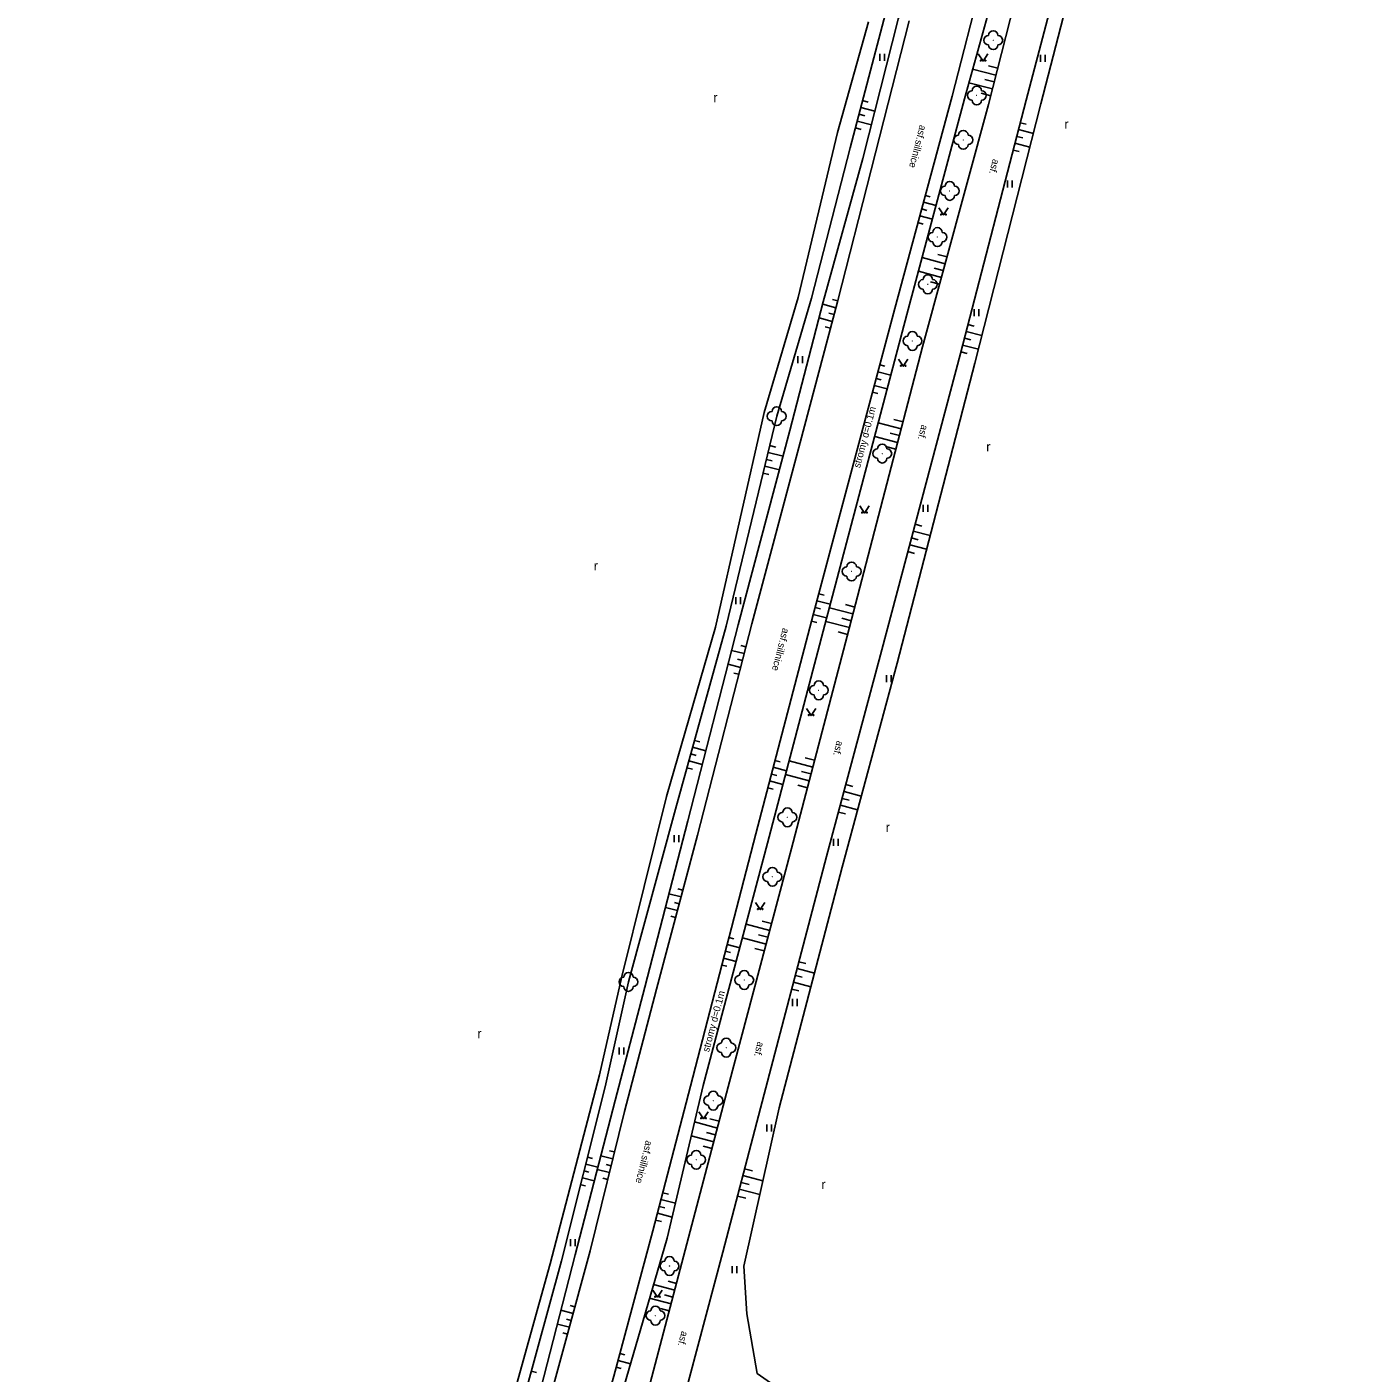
# Model space of a CAD drawing. Extents: x -544674 to -541478, y -1199076 to -1195527.
# Drawn here: x -543780.2 to -543639.1, y -1196517.3 to -1196374.7 of the extents above; entities that cross this region are included whole.
import ezdxf

# ---------------------------------------------------------------- set-up
doc = ezdxf.new("R2010")
doc.units = 0
for name, color, linetype in [('POMOC_POPIS', 7, 'Continuous'), ('ROZHRANÍ_PLOCH', 7, 'Continuous'), ('VÝŠKOPIS', 7, 'Continuous'), ('ZELEŇ', 7, 'Continuous'), ('ZN_KULTUR', 7, 'Continuous')]:
    doc.layers.add(name, color=color, linetype=linetype)

msp = doc.modelspace()

# ---------------------------------------------------------------- linework, layer by layer
at = {"layer": 'ROZHRANÍ_PLOCH'}
for points in [[(-543713.94, -1196502.29), (-543709.96, -1196486.96), (-543703.04, -1196460.2), (-543696.91, -1196436.86), (-543688.3, -1196404.54), (-543682.23, -1196382.06), (-543675.78, -1196357.01), (-543668.72, -1196330.57), (-543660.24, -1196299.58), (-543653.67, -1196274.57), (-543648.76, -1196256.23)], [(-543710.32, -1196503.65), (-543705.94, -1196487.01), (-543699.25, -1196461.77), (-543693.35, -1196439.26), (-543685.35, -1196408.6), (-543678.38, -1196382.95), (-543671.9, -1196357.54), (-543664.83, -1196330.47), (-543656.54, -1196299.56), (-543650.01, -1196274.95), (-543645.18, -1196256.3)], [(-543706.53, -1196504.53), (-543702.52, -1196489.26), (-543695.52, -1196462.6), (-543689.68, -1196440.73), (-543681.35, -1196409.31), (-543674.39, -1196382.48), (-543667.96, -1196358.03), (-543660.58, -1196330.51), (-543652.53, -1196299.96), (-543646.07, -1196275.64), (-543641, -1196257.05)], [(-543686.78, -1196374.08), (-543690.8, -1196389.86), (-543694.38, -1196403.86), (-543698.34, -1196418.74), (-543703.44, -1196437.95), (-543709.2, -1196460.36), (-543713.55, -1196476.67), (-543716.95, -1196489.63), (-543720.59, -1196504.4), (-543725.61, -1196522.92), (-543729.11, -1196534.77), (-543733.49, -1196548.27), (-543738.89, -1196562.11), (-543744.58, -1196575.93), (-543749.39, -1196586.97), (-543754.95, -1196599.21), (-543755.34, -1196599.22), (-543756.54, -1196598.46), (-543756.94, -1196599.56), (-543760.03, -1196600.31), (-543763.62, -1196598.81)], [(-543729.73, -1196565.54), (-543730.89, -1196565.83), (-543732.83, -1196565.23), (-543733.3, -1196563.99), (-543732.97, -1196562.92), (-543728.03, -1196551.04), (-543722.51, -1196533.16), (-543718.06, -1196517.68), (-543713.94, -1196502.29)], [(-543729.73, -1196565.54), (-543725.15, -1196555.44), (-543719.77, -1196539.74), (-543714.56, -1196519.74), (-543710.32, -1196503.65)], [(-543710.94, -1196521.13), (-543706.53, -1196504.53)]]:
    msp.add_lwpolyline(points, dxfattribs=at)
at = {"layer": 'VÝŠKOPIS'}
for points in [[(-543656.57, -1196252.62), (-543662.82, -1196274.48), (-543668.53, -1196296.88), (-543674.74, -1196318.16), (-543679.23, -1196336.73), (-543684.9, -1196357.49), (-543689.3, -1196373.31), (-543693.03, -1196387.54), (-543697.13, -1196403.44), (-543700.81, -1196415.96), (-543706.15, -1196438.21), (-543711.55, -1196457.59), (-543716.52, -1196475.9), (-543718.99, -1196487.01), (-543723.6, -1196505.47), (-543727.55, -1196519.79), (-543731.43, -1196534.94), (-543734.91, -1196546.82), (-543740.91, -1196561.15), (-543746.57, -1196574.16), (-543754.01, -1196590.99), (-543756.54, -1196598.46)], [(-543655.56, -1196252.24), (-543661.88, -1196275.79), (-543667.34, -1196296.39), (-543673.37, -1196318.85), (-543677.88, -1196336.4), (-543683.81, -1196358.79), (-543687.96, -1196373.9), (-543691.68, -1196388.67), (-543695.88, -1196403.86), (-543699.42, -1196417.47), (-543704.89, -1196438.05), (-543710.23, -1196458.84), (-543714.8, -1196476.45), (-543717.94, -1196488.46), (-543722.17, -1196504.83), (-543726.47, -1196521.6), (-543730.21, -1196534.99), (-543734.23, -1196547.47), (-543745.4, -1196574.89), (-543750.67, -1196586.8), (-543755.95, -1196598.6)], [(-543712.43, -1196503.05), (-543708.6, -1196486.87), (-543701.78, -1196461.21), (-543695.71, -1196438.06), (-543687.01, -1196405.18), (-543680.92, -1196382.32), (-543674.04, -1196357.52), (-543666.62, -1196330.61), (-543658.6, -1196299.62), (-543651.87, -1196274.66), (-543647, -1196256.04)], [(-543677.4, -1196379.1), (-543678.38, -1196378.85)], [(-543677.58, -1196379.83), (-543680.05, -1196379.2)], [(-543677.77, -1196380.55), (-543678.76, -1196380.3)], [(-543677.95, -1196381.28), (-543680.45, -1196380.64)], [(-543678.14, -1196382.01), (-543679.15, -1196381.75)], [(-543691.9, -1196383.24), (-543690.41, -1196383.63)], [(-543691.71, -1196382.52), (-543691.12, -1196382.67)], [(-543692.28, -1196384.69), (-543690.78, -1196385.09)], [(-543692.09, -1196383.97), (-543691.49, -1196384.12)], [(-543692.47, -1196385.42), (-543691.87, -1196385.58)], [(-543675.19, -1196385.58), (-543673.62, -1196385.99)], [(-543675.01, -1196384.86), (-543674.38, -1196385.02)], [(-543675.57, -1196387.03), (-543673.99, -1196387.45)], [(-543675.38, -1196386.31), (-543674.75, -1196386.47)], [(-543675.76, -1196387.76), (-543675.13, -1196387.93)], [(-543685.06, -1196392.56), (-543684.54, -1196392.7)], [(-543685.45, -1196394), (-543684.92, -1196394.15)], [(-543685.26, -1196393.28), (-543683.93, -1196393.64)], [(-543685.85, -1196395.45), (-543685.31, -1196395.6)], [(-543685.65, -1196394.73), (-543684.32, -1196395.09)], [(-543682.76, -1196399.08), (-543683.74, -1196398.82)], [(-543682.96, -1196399.81), (-543685.4, -1196399.14)], [(-543683.16, -1196400.53), (-543684.13, -1196400.26)], [(-543683.35, -1196401.25), (-543685.79, -1196400.59)], [(-543683.55, -1196401.98), (-543684.52, -1196401.71)], [(-543694.54, -1196404.47), (-543695.94, -1196404.1)], [(-543694.35, -1196403.74), (-543694.91, -1196403.6)], [(-543694.93, -1196405.92), (-543696.32, -1196405.55)], [(-543694.73, -1196405.19), (-543695.29, -1196405.04)], [(-543695.12, -1196406.64), (-543695.68, -1196406.49)], [(-543680.74, -1196406.97), (-543679.07, -1196407.4)], [(-543680.55, -1196406.24), (-543679.89, -1196406.42)], [(-543681.12, -1196408.42), (-543679.44, -1196408.86)], [(-543680.93, -1196407.7), (-543680.26, -1196407.87)], [(-543681.31, -1196409.15), (-543680.64, -1196409.32)], [(-543690.09, -1196411.25), (-543688.71, -1196411.61)], [(-543689.89, -1196410.52), (-543689.34, -1196410.67)], [(-543690.47, -1196412.69), (-543689.1, -1196413.06)], [(-543690.28, -1196411.97), (-543689.73, -1196412.12)], [(-543690.67, -1196413.42), (-543690.11, -1196413.57)], [(-543687.62, -1196417.29), (-543690.05, -1196416.65)], [(-543687.43, -1196416.56), (-543688.4, -1196416.31)], [(-543688, -1196418.74), (-543690.43, -1196418.1)], [(-543687.81, -1196418.01), (-543688.78, -1196417.76)], [(-543701.73, -1196419.81), (-543700.14, -1196420.19)], [(-543701.56, -1196419.08), (-543700.92, -1196419.24)], [(-543688.18, -1196419.46), (-543689.16, -1196419.21)], [(-543702.08, -1196421.27), (-543700.53, -1196421.64)], [(-543701.91, -1196420.54), (-543701.28, -1196420.69)], [(-543702.26, -1196422), (-543701.64, -1196422.15)], [(-543686.15, -1196427.41), (-543685.44, -1196427.6)], [(-543686.53, -1196428.86), (-543685.82, -1196429.05)], [(-543686.34, -1196428.13), (-543684.56, -1196428.6)], [(-543686.92, -1196430.31), (-543686.2, -1196430.5)], [(-543686.72, -1196429.58), (-543684.93, -1196430.06)], [(-543696.55, -1196435.51), (-543695.13, -1196435.88)], [(-543696.36, -1196434.78), (-543695.79, -1196434.93)], [(-543692.55, -1196436.18), (-543693.54, -1196435.92)], [(-543696.94, -1196436.96), (-543695.52, -1196437.33)], [(-543696.74, -1196436.23), (-543696.18, -1196436.38)], [(-543692.74, -1196436.9), (-543695.23, -1196436.25)], [(-543692.92, -1196437.63), (-543693.92, -1196437.37)], [(-543697.13, -1196437.68), (-543696.56, -1196437.83)], [(-543693.11, -1196438.36), (-543695.62, -1196437.7)], [(-543693.3, -1196439.08), (-543694.3, -1196438.82)], [(-543704.07, -1196440.4), (-543704.6, -1196440.26)], [(-543704.26, -1196441.12), (-543705.59, -1196440.78)], [(-543704.44, -1196441.85), (-543704.98, -1196441.71)], [(-543704.63, -1196442.58), (-543705.96, -1196442.23)], [(-543704.82, -1196443.3), (-543705.35, -1196443.17)], [(-543709.52, -1196450.31), (-543708.97, -1196450.46)], [(-543709.92, -1196451.75), (-543709.36, -1196451.91)], [(-543709.72, -1196451.03), (-543708.32, -1196451.42)], [(-543710.12, -1196452.48), (-543708.7, -1196452.87)], [(-543701.19, -1196453.16), (-543699.77, -1196453.54)], [(-543701, -1196452.44), (-543700.43, -1196452.59)], [(-543696.99, -1196453.14), (-543699.49, -1196452.49)], [(-543696.8, -1196452.42), (-543697.8, -1196452.16)], [(-543710.33, -1196453.2), (-543709.75, -1196453.36)], [(-543701.38, -1196453.89), (-543700.81, -1196454.04)], [(-543697.37, -1196454.59), (-543699.87, -1196453.94)], [(-543697.18, -1196453.87), (-543698.18, -1196453.61)], [(-543701.76, -1196455.34), (-543701.19, -1196455.49)], [(-543701.57, -1196454.61), (-543700.15, -1196454.99)], [(-543697.56, -1196455.32), (-543698.56, -1196455.06)], [(-543693.68, -1196455.72), (-543691.85, -1196456.22)], [(-543693.49, -1196455), (-543692.75, -1196455.2)], [(-543694.07, -1196457.17), (-543692.24, -1196457.66)], [(-543693.88, -1196456.45), (-543693.14, -1196456.65)], [(-543694.26, -1196457.9), (-543693.53, -1196458.09)], [(-543710.94, -1196466.89), (-543712.23, -1196466.55)], [(-543710.75, -1196466.17), (-543711.27, -1196466.03)], [(-543711.33, -1196468.34), (-543712.61, -1196468)], [(-543711.14, -1196467.62), (-543711.65, -1196467.48)], [(-543711.52, -1196469.07), (-543712.03, -1196468.93)], [(-543701.55, -1196470.45), (-543704.06, -1196469.78)], [(-543701.36, -1196469.72), (-543702.36, -1196469.46)], [(-543705.88, -1196471.2), (-543705.34, -1196471.34)], [(-543701.93, -1196471.9), (-543704.44, -1196471.23)], [(-543701.74, -1196471.17), (-543702.75, -1196470.91)], [(-543706.26, -1196472.65), (-543705.72, -1196472.79)], [(-543706.07, -1196471.93), (-543704.72, -1196472.28)], [(-543702.13, -1196472.62), (-543703.13, -1196472.36)], [(-543706.64, -1196474.11), (-543706.1, -1196474.24)], [(-543706.45, -1196473.38), (-543705.11, -1196473.73)], [(-543698.64, -1196474.49), (-543696.81, -1196474.97)], [(-543698.45, -1196473.76), (-543697.72, -1196473.95)], [(-543699.02, -1196475.94), (-543697.19, -1196476.42)], [(-543698.83, -1196475.21), (-543698.1, -1196475.4)], [(-543699.21, -1196476.66), (-543698.48, -1196476.86)], [(-543707.09, -1196491.38), (-543709.52, -1196490.74)], [(-543706.9, -1196490.66), (-543707.88, -1196490.4)], [(-543707.47, -1196492.83), (-543709.86, -1196492.2)], [(-543707.28, -1196492.11), (-543708.24, -1196491.85)], [(-543720.85, -1196494.48), (-543720.34, -1196494.6)], [(-543718.19, -1196494.64), (-543719.46, -1196494.33)], [(-543718.01, -1196493.91), (-543718.51, -1196493.79)], [(-543707.66, -1196493.56), (-543708.61, -1196493.31)], [(-543721.22, -1196495.93), (-543720.71, -1196496.06)], [(-543721.04, -1196495.2), (-543719.76, -1196495.52)], [(-543718.54, -1196496.1), (-543719.83, -1196495.78)], [(-543718.36, -1196495.37), (-543718.88, -1196495.24)], [(-543704.21, -1196495.69), (-543703.37, -1196495.91)], [(-543721.58, -1196497.39), (-543721.08, -1196497.51)], [(-543721.4, -1196496.66), (-543720.14, -1196496.97)], [(-543718.72, -1196496.83), (-543719.24, -1196496.7)], [(-543704.59, -1196497.14), (-543703.73, -1196497.36)], [(-543704.4, -1196496.41), (-543702.28, -1196496.97)], [(-543712.89, -1196498.23), (-543712.28, -1196498.39)], [(-543704.97, -1196498.59), (-543704.09, -1196498.82)], [(-543704.78, -1196497.86), (-543702.61, -1196498.43)], [(-543713.26, -1196499.68), (-543712.65, -1196499.84)], [(-543713.08, -1196498.96), (-543711.55, -1196499.35)], [(-543713.64, -1196501.14), (-543713.01, -1196501.3)], [(-543713.45, -1196500.41), (-543711.9, -1196500.81)], [(-543731.34, -1196564.06), (-543726.83, -1196552.9), (-543721.06, -1196533.73), (-543717.02, -1196518.81), (-543712.43, -1196503.05)], [(-543711.62, -1196508.57), (-543713.86, -1196507.97)], [(-543711.42, -1196507.84), (-543712.32, -1196507.61)], [(-543722.19, -1196510.32), (-543722.71, -1196510.18)], [(-543712, -1196510.02), (-543714.28, -1196509.42)], [(-543711.81, -1196509.29), (-543712.71, -1196509.05)], [(-543722.39, -1196511.04), (-543723.67, -1196510.69)], [(-543722.59, -1196511.77), (-543723.1, -1196511.63)], [(-543712.19, -1196510.74), (-543713.11, -1196510.5)], [(-543722.78, -1196512.49), (-543724.05, -1196512.15)], [(-543722.98, -1196513.21), (-543723.48, -1196513.08)], [(-543717.42, -1196515.28), (-543716.89, -1196515.42)], [(-543726.82, -1196517.14), (-543726.26, -1196517.29)], [(-543717.81, -1196516.73), (-543717.29, -1196516.87)], [(-543717.61, -1196516.01), (-543716.31, -1196516.36)]]:
    msp.add_lwpolyline(points, dxfattribs=at)
at = {"layer": 'ZELEŇ'}
for points in [[(-543688.28, -1196527.59), (-543702.87, -1196517.4), (-543703.99, -1196511.08), (-543704.31, -1196506.02), (-543700.55, -1196489.23), (-543693.87, -1196463.75), (-543688.06, -1196442.12), (-543679.82, -1196410.33), (-543672.82, -1196382.86), (-543666.5, -1196358.38), (-543659.09, -1196330.75), (-543650.58, -1196299.71), (-543644.42, -1196276.01), (-543639.11, -1196257.26)], [(-543691.1, -1196374.18), (-543694.38, -1196385.9), (-543698.54, -1196403.39), (-543702.15, -1196415.58), (-543707.3, -1196438.33), (-543712.47, -1196456.25), (-543717.21, -1196475.32), (-543719.59, -1196485.76), (-543724.81, -1196505.77), (-543728.19, -1196517.96), (-543732.69, -1196534.82), (-543736.53, -1196544.77), (-543742.92, -1196560.89), (-543747.83, -1196573.44), (-543753.43, -1196587.09), (-543757.29, -1196589.64), (-543761.72, -1196591.39), (-543770.74, -1196589.32), (-543780.25, -1196585.27)]]:
    msp.add_lwpolyline(points, dxfattribs=at)
for centre in [(-543677.87, -1196376.12), (-543679.61, -1196381.98), (-543681.04, -1196386.68), (-543682.47, -1196392.09), (-543683.78, -1196396.98), (-543684.8, -1196401.99), (-543686.43, -1196407.99), (-543700.81, -1196415.96), (-543689.63, -1196419.92), (-543692.87, -1196432.41), (-543696.35, -1196445), (-543699.68, -1196458.46), (-543701.27, -1196464.76), (-543716.52, -1196475.9), (-543704.25, -1196475.7), (-543706.15, -1196482.87), (-543707.53, -1196488.48), (-543709.34, -1196494.75), (-543712.17, -1196506), (-543713.66, -1196511.26)]:
    msp.add_circle(centre, 0.0005, dxfattribs=at)
for centre, start, end in [((-543678.37, -1196376.12), 89.99999, 269.99999), ((-543677.87, -1196375.62), 0, 179.99999), ((-543677.37, -1196376.12), 270, 89.99999), ((-543677.87, -1196376.62), 179.99999, 359.99999), ((-543680.11, -1196381.98), 89.99999, 269.99999), ((-543679.61, -1196381.48), 0, 179.99999), ((-543679.11, -1196381.98), 270, 89.99999), ((-543679.61, -1196382.48), 179.99999, 359.99999), ((-543681.04, -1196386.18), 0, 179.99999), ((-543681.54, -1196386.68), 89.99999, 269.99999), ((-543681.04, -1196387.18), 179.99999, 359.99999), ((-543680.54, -1196386.68), 270, 89.99999), ((-543682.97, -1196392.09), 89.99999, 269.99999), ((-543682.47, -1196391.59), 0, 179.99999), ((-543681.97, -1196392.09), 270, 89.99999), ((-543682.47, -1196392.59), 179.99999, 359.99999), ((-543683.78, -1196396.48), 0, 179.99999), ((-543684.28, -1196396.98), 89.99999, 269.99999), ((-543683.78, -1196397.48), 179.99999, 359.99999), ((-543683.28, -1196396.98), 270, 89.99999), ((-543685.3, -1196401.99), 89.99999, 269.99999), ((-543684.8, -1196401.49), 0, 179.99999), ((-543684.3, -1196401.99), 270, 89.99999), ((-543684.8, -1196402.49), 179.99999, 359.99999), ((-543686.93, -1196407.99), 89.99999, 269.99999), ((-543686.43, -1196407.49), 0, 179.99999), ((-543685.93, -1196407.99), 270, 89.99999), ((-543686.43, -1196408.49), 179.99999, 359.99999), ((-543701.31, -1196415.96), 89.99999, 269.99999), ((-543700.81, -1196415.46), 0, 179.99999), ((-543700.31, -1196415.96), 270, 89.99999), ((-543700.81, -1196416.46), 179.99999, 359.99999), ((-543689.63, -1196419.42), 0, 179.99999), ((-543690.13, -1196419.92), 89.99999, 269.99999), ((-543689.13, -1196419.92), 270, 89.99999), ((-543689.63, -1196420.42), 179.99999, 359.99999), ((-543692.87, -1196431.91), 0, 179.99999), ((-543693.37, -1196432.41), 89.99999, 269.99999), ((-543692.87, -1196432.91), 179.99999, 359.99999), ((-543692.37, -1196432.41), 270, 89.99999), ((-543696.85, -1196445), 89.99999, 269.99999), ((-543696.35, -1196444.5), 0, 179.99999), ((-543695.85, -1196445), 270, 89.99999), ((-543696.35, -1196445.5), 179.99999, 359.99999), ((-543699.68, -1196457.96), 0, 179.99999), ((-543700.18, -1196458.46), 89.99999, 269.99999), ((-543699.18, -1196458.46), 270, 89.99999), ((-543699.68, -1196458.96), 179.99999, 359.99999), ((-543701.77, -1196464.76), 89.99999, 269.99999), ((-543701.27, -1196464.26), 0, 179.99999), ((-543700.77, -1196464.76), 270, 89.99999), ((-543701.27, -1196465.26), 179.99999, 359.99999), ((-543717.02, -1196475.9), 89.99999, 269.99999), ((-543716.52, -1196475.4), 0, 179.99999), ((-543716.02, -1196475.9), 270, 89.99999), ((-543704.75, -1196475.7), 89.99999, 269.99999), ((-543704.25, -1196475.2), 0, 179.99999), ((-543703.75, -1196475.7), 270, 89.99999), ((-543716.52, -1196476.4), 179.99999, 359.99999), ((-543704.25, -1196476.2), 179.99999, 359.99999), ((-543706.65, -1196482.87), 89.99999, 269.99999), ((-543706.15, -1196482.37), 0, 179.99999), ((-543705.65, -1196482.87), 270, 89.99999), ((-543706.15, -1196483.37), 179.99999, 359.99999), ((-543708.03, -1196488.48), 89.99999, 269.99999), ((-543707.53, -1196487.98), 0, 179.99999), ((-543707.03, -1196488.48), 270, 89.99999), ((-543707.53, -1196488.98), 179.99999, 359.99999), ((-543709.84, -1196494.75), 89.99999, 269.99999), ((-543709.34, -1196494.25), 0, 179.99999), ((-543708.84, -1196494.75), 270, 89.99999), ((-543709.34, -1196495.25), 179.99999, 359.99999), ((-543712.67, -1196506), 89.99999, 269.99999), ((-543712.17, -1196505.5), 0, 179.99999), ((-543711.67, -1196506), 270, 89.99999), ((-543712.17, -1196506.5), 179.99999, 359.99999), ((-543714.16, -1196511.26), 89.99999, 269.99999), ((-543713.66, -1196510.76), 0, 179.99999), ((-543713.16, -1196511.26), 270, 89.99999), ((-543713.66, -1196511.76), 179.99999, 359.99999)]:
    msp.add_arc(centre, 0.5, start, end, dxfattribs=at)
at = {"layer": 'ZN_KULTUR'}
for p, q in [((-543689.9, -1196378.315), (-543689.9, -1196377.565)), ((-543689.4, -1196378.315), (-543689.4, -1196377.565)), ((-543672.86, -1196378.425), (-543672.86, -1196377.675)), ((-543672.36, -1196378.425), (-543672.36, -1196377.675)), ((-543676.36, -1196391.745), (-543676.36, -1196390.995)), ((-543675.86, -1196391.745), (-543675.86, -1196390.995)), ((-543679.9, -1196405.355), (-543679.9, -1196404.605)), ((-543679.4, -1196405.355), (-543679.4, -1196404.605)), ((-543698.57, -1196410.335), (-543698.57, -1196409.585)), ((-543698.07, -1196410.335), (-543698.07, -1196409.585)), ((-543685.3, -1196426.105), (-543685.3, -1196425.355)), ((-543684.8, -1196426.105), (-543684.8, -1196425.355)), ((-543705.13, -1196435.885), (-543705.13, -1196435.135)), ((-543704.63, -1196435.885), (-543704.63, -1196435.135)), ((-543689.19, -1196444.145), (-543689.19, -1196443.395)), ((-543688.69, -1196444.145), (-543688.69, -1196443.395)), ((-543711.68, -1196461.105), (-543711.68, -1196460.355)), ((-543711.18, -1196461.105), (-543711.18, -1196460.355)), ((-543694.81, -1196461.485), (-543694.81, -1196460.735)), ((-543694.31, -1196461.485), (-543694.31, -1196460.735)), ((-543699.15, -1196478.455), (-543699.15, -1196477.705)), ((-543698.65, -1196478.455), (-543698.65, -1196477.705)), ((-543717.5, -1196483.585), (-543717.5, -1196482.835)), ((-543717, -1196483.585), (-543717, -1196482.835)), ((-543701.87, -1196491.745), (-543701.87, -1196490.995)), ((-543701.37, -1196491.745), (-543701.37, -1196490.995)), ((-543722.66, -1196503.915), (-543722.66, -1196503.165)), ((-543722.16, -1196503.915), (-543722.16, -1196503.165)), ((-543705.53, -1196506.765), (-543705.53, -1196506.015)), ((-543705.03, -1196506.765), (-543705.03, -1196506.015))]:
    msp.add_line(p, q, dxfattribs=at)
for points in [[(-543679.45, -1196377.58), (-543678.95, -1196378.33), (-543678.45, -1196377.58)], [(-543683.64, -1196393.89), (-543683.14, -1196394.64), (-543682.64, -1196393.89)], [(-543687.91, -1196409.91), (-543687.41, -1196410.66), (-543686.91, -1196409.91)], [(-543692.01, -1196425.47), (-543691.51, -1196426.22), (-543691.01, -1196425.47)], [(-543697.67, -1196446.93), (-543697.17, -1196447.68), (-543696.67, -1196446.93)], [(-543703.06, -1196467.49), (-543702.56, -1196468.24), (-543702.06, -1196467.49)], [(-543709.07, -1196489.65), (-543708.57, -1196490.4), (-543708.07, -1196489.65)], [(-543713.94, -1196508.55), (-543713.44, -1196509.3), (-543712.94, -1196508.55)]]:
    msp.add_lwpolyline(points, dxfattribs=at)
for centre in [(-543679.2, -1196378.28), (-543678.7, -1196378.28), (-543683.39, -1196394.59), (-543682.89, -1196394.59), (-543687.66, -1196410.61), (-543687.16, -1196410.61), (-543691.76, -1196426.17), (-543691.26, -1196426.17), (-543697.42, -1196447.63), (-543696.92, -1196447.63), (-543702.81, -1196468.19), (-543702.31, -1196468.19), (-543708.82, -1196490.35), (-543708.32, -1196490.35), (-543713.69, -1196509.25), (-543713.19, -1196509.25)]:
    msp.add_circle(centre, 0.05, dxfattribs=at)

# ---------------------------------------------------------------- texts
at = {"layer": 'POMOC_POPIS'}
for s, rotation, p in [('asf.sillnice', 255.70774, (-543685.65, -1196385.06)), ('asf.', 254.79782, (-543677.9, -1196388.66)), ('asf.', 255.22483, (-543685.46, -1196416.81)), ('asf.sillnice', 255.58539, (-543700.17, -1196438.36)), ('asf.', 255.31283, (-543694.43, -1196450.29)), ('asf.', 255.1548, (-543702.82, -1196482.18)), ('asf.sillnice', 256.15559, (-543714.67, -1196492.65)), ('asf.', 255.23716, (-543710.89, -1196512.85))]:
    msp.add_text(s, height=0.75, rotation=rotation, dxfattribs=at).set_placement(p)
at = {"layer": 'ZELEŇ'}
for rotation, p in [(75.17927, (-543691.99, -1196421.49)), (75.11585, (-543707.99, -1196483.39))]:
    msp.add_text('stromy d=0.1m', height=0.75, rotation=rotation, dxfattribs=at).set_placement(p)
at = {"layer": 'ZN_KULTUR'}
for p in [(-543707.528, -1196382.702), (-543670.338, -1196385.512), (-543678.608, -1196419.692), (-543720.188, -1196432.302), (-543689.258, -1196460.012), (-543732.528, -1196481.872), (-543696.078, -1196497.852)]:
    msp.add_text('r', height=1, dxfattribs=at).set_placement(p)

doc.saveas('drawing.dxf')
